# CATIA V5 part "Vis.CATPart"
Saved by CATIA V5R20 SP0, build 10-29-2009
Part number: Vis
Bounding box of the stored display mesh (mm): x -29.774 to -18.226, y 19.5 to 71.5, z -16 to -6
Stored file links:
  E:\Boulot\SeaTech\2eme ANNEE\FabricationAdditive\TP_MOSM_CREM\Projet Sauterelle de serrage\CAO Assemblage Sauterelle\Vis.CATPart
  E:\Boulot\SeaTech\2eme ANNEE\FabricationAdditive\TP_MOSM_CREM\Projet Sauterelle de serrage\CAO Assemblage Sauterelle\Sauterelle_horizontale_05120-06.CATPart
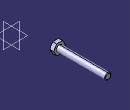
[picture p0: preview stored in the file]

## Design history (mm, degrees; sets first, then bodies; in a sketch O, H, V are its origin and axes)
Body1 (main body)
  Solid1 "05120-06_11": solid without history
